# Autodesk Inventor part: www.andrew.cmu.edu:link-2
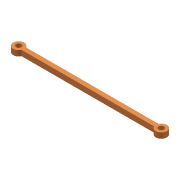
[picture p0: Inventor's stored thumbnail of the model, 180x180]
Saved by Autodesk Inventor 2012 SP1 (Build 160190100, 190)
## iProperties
Shininess: 64.0
Angle Display Precision: 2
Document Length Units: 11272
Document Angle Units: 11279
Document Time Units: 11290
Document Mass Units: 11286
Document Length Units Precision: 3
Document Angle Units Precision: 2
Created: 2008-04
Material: Aluminum-6061
Document SubType Name: Modeling
Density: 2.71 g/cm^3
Mass: 19.9836 g
Surface Area: 49.5521 cm^2
Volume: 7.374 cm^3
Density: 7.75
Volumn: 7.373977547129407
Area: 49.55207478872388
PropertySet Name: Model Information
Control State: 0
Master: False
Checked Out: False
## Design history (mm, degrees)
sketch "Sketch1"
  geometry: L1 (53.998, -31.646)-(-99.462, -31.646); L2 (53.998, -36.726)-(-99.462, -36.726); A1 r 6.35 centre (59.818, -34.186) between (53.998, -36.726) and (53.998, -31.646); A2 r 6.35 centre (-105.282, -34.186) between (-99.462, -31.646) and (-99.462, -36.726)
  constraints: 4 end point, 4 point on circle, 2 centre point, 1 horizontal, 1 parallel, 1 other
  dimensions: "d1" = 6.35 radius of A1; "d3" = 5.08 distance between parallel lines of L1 L2; "d5" = 165.1 distance of A1.centre A2.centre; "d7" = 6.35 radius of A2; "d27" = 2.54 distance from line of L1 A2.centre (= 0.5 x d3)
extrude "ExtrusionMidplane1" new body sketch "Sketch1" stored distance "d9" = 6.35; taper "d10" = 0 deg
sketch "Sketch2"
  geometry: A1 r 6.35 centre (105.282, -34.186) between (99.462, -36.726) and (99.462, -31.646) reference; 1 further point
hole "Hole1" sketch "Sketch2" at (105.282, -34.186) diameter "d13" = 6.35; stored, may be unused: countersink angle "d17" = 82 deg, drill point angle "d19" = 118 deg; dims "d14" = 12.7, "d15" = 9.525, "d16" = 6.35, "d18" = 19.05
sketch "Sketch3"
  geometry: A1 r 6.35 centre (59.818, -34.186) between (53.998, -36.726) and (53.998, -31.646) reference; 1 further point
hole "Hole2" sketch "Sketch3" at (59.818, -34.186) diameter "d20" = 6.35; stored, may be unused: countersink angle "d24" = 82 deg, drill point angle "d26" = 118 deg; dims "d21" = 12.7, "d22" = 9.525, "d23" = 6.35, "d25" = 19.05
body "Solid1"
other parameters: "d0" = 6.35 (derived), "d2" = 6.35 (derived), "d4" = 165.1 (derived), "d6" = 6.35 (derived), "d8" = 0 (derived), "d11" = 0, "d12" = 0
